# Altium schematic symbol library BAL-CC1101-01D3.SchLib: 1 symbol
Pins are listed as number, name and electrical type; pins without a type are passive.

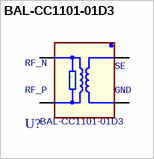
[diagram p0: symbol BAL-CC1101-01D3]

## BAL-CC1101-01D3
designator U?
footprint ST_CSP4N50x120P2x2_202x105x69 (Footprint not found)
pins: A1 SE, A2 RF_N, B1 GND, B2 RF_P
